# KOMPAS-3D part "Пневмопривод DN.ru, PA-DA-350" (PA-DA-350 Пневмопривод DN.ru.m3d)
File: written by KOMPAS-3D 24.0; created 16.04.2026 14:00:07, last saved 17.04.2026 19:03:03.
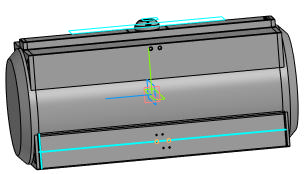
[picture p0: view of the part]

Document properties: Автор: DN.ru; Полное имя файла: C:\Работа\PA-DA-х Пневмопривод DN.ru\350\исходные материалы\PA-DA-350 Пневмопривод DN.ru.m3d

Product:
- Body: Тело 1  | qty 1
    Масса: 988.452769
- Body: Тело 2  | qty 1
    Масса: 988.452769
- Part/product: Пневмопривод DN.ru  | designation PA-DA-350
    Масса: 186
    Раздел спецификации: Прочие изделия
    Примечание: D290-00303

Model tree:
1. Эскиз:1
2. Элемент выдавливания:1
3. Эскиз:2  (with: Ребро.Элемент выдавливания:1)
4. Элемент выдавливания:2
5. Эскиз:3  (with: Ребро.Элемент выдавливания:2)
6. Элемент выдавливания:3  (with: Грань.Элемент выдавливания:2)
     Смещение 1 = -2; Расстояние 2 = 418; Смещение 2 = -2
7. Эскиз:4  (with: Грань.Элемент выдавливания:3)
8. Элемент выдавливания:4
9. Эскиз:6  (with: Ребро.Элемент выдавливания:2, Ребро.Элемент выдавливания:1)
10. Элемент выдавливания:6
11. Средняя плоскость:1  (with: Грань.Элемент выдавливания:6)
12. Отверстие:2  (with: Грань.Элемент выдавливания:6)
     Глубина выреза = 10; Диаметр отверстия = 6; Угол конуса дна = 120; Расстояние 2 = -22.5
13. Массив по сетке:2  (with: Отверстие:2)  (3 pattern instances)
     Шаг 1 = 20; Угол раствора = 90; Шаг 2 = 45
14. Массив по сетке:3  (with: Отверстие:2)  (2 pattern instances)
     Шаг 1 = 45; Угол раствора = 90; Шаг 2 = 20
15. Отверстие:3  (with: Грань.Элемент выдавливания:6)  (labels: W 1/2'')
     Глубина выреза = 10; Диаметр отверстия = 9.98886; Угол конуса дна = 120; Расстояние 1 = 20
16. W 1/2''  (with: Грань.Отверстие:3, Грань.Элемент выдавливания:6)  (labels: cil5_ex_DIN 477 BSW coarse)
     Длина резьбы = 8; Шаг резьбы = 2.117; Номинальный диаметр резьбы = 12.7
17. Массив по сетке:4  (with: Отверстие:3)  (labels: W 1/2'')  (2 pattern instances)
18. W 1/4''  (with: Грань.Отверстие:3, Грань.Элемент выдавливания:6)  (labels: cil5_ex_DIN 477 BSW coarse)
     Длина резьбы = 8; Шаг резьбы = 2.117; Номинальный диаметр резьбы = 12.7; Шаг 1 = 40; Угол раствора = 90; Шаг 2 = 10
19. Эскиз:7  (with: Грань.Элемент выдавливания:2)
20. Элемент выдавливания:7
21. Эскиз:8  (with: Грань.Элемент выдавливания:2, Ребро.Элемент выдавливания:2)
22. Элемент выдавливания:8  (with: Грань.Элемент выдавливания:6)
     Расстояние 2 = 4
23. Отверстие:4  (with: Грань.Элемент выдавливания:2)
     Глубина выреза = 7; Диаметр отверстия = 10; Угол конуса дна = 118; Расстояние 1 = 15; Расстояние 2 = 15; Диаметр зенковки = 13.2; Глубина зенковки = 1.6; Угол зенковки = 90
24. Массив по сетке:5  (with: Отверстие:4)  (2 pattern instances)
     Шаг 1 = 30; Угол раствора = 90
25. Отверстие:5  (with: Грань.Элемент выдавливания:3)
     Глубина выреза = 10; Диаметр отверстия = 5; Угол конуса дна = 120; Диаметр зенковки = 7; Глубина зенковки = 1; Угол зенковки = 90
26. Массив по сетке:6  (with: Отверстие:5)  (4 pattern instances)
     Угол раствора = 90
27. Фаска:1  (with: Ребро.Элемент выдавливания:4)
     Угол = 45; Длина 1 = 15; Длина 2 = 15
28. Скругление:2  (with: Ребро.Элемент выдавливания:3)
     Радиус = 2
29. Скругление:3  (with: Ребро.Элемент выдавливания:6)
     Радиус = 3
30. Скругление:4  (with: Ребро.Элемент выдавливания:8, Ребро.Элемент выдавливания:2)
     Радиус = 2
31. Скругление:5  (with: Ребро.Элемент выдавливания:6)
     Радиус = 3
32. Смещенная плоскость:1  (with: Грань.Элемент выдавливания:3)
33. Эскиз:9
34. Элемент выдавливания:9  (with: Грань.Фаска:1)
     Расстояние 1 = 43.4142; Смещение 1 = 1
35. Смещенная плоскость:2  (with: Грань.Элемент выдавливания:4)
     Расстояние = 0.5
36. Эскиз:10
37. Элемент выдавливания:10
     Расстояние 1 = 25.9142
38. Эскиз:11  (with: Грань.Элемент выдавливания:4)
39. Элемент выдавливания:11
     Расстояние 1 = 1
40. Эскиз:12  (with: Грань.Элемент выдавливания:11, Ребро.Элемент выдавливания:11)
41. Элемент выдавливания:12  (with: Грань.Элемент выдавливания:4)
     Расстояние 2 = 1
42. Эскиз:13  (with: Грань.Элемент выдавливания:11)
43. Элемент выдавливания:13  (with: Грань.Элемент выдавливания:4)
     Расстояние 2 = 1
44. Скругление:7  (with: Ребро.Элемент выдавливания:11)
     Радиус = 1
45. Скругление:8  (with: Ребро.Элемент выдавливания:8)
     Радиус = 2
46. Эскиз:14  (with: Грань.Элемент выдавливания:3)
47. Элемент выдавливания:14  (with: Грань.Фаска:1)
     Расстояние 1 = 54.1414; Смещение 1 = 0.1
48. Эскиз:15  (with: Грань.Элемент выдавливания:3, Ребро.Скругление:2)
49. Элемент выдавливания:15
     Расстояние 2 = 0.1
50. Отверстие:6  (with: Грань.Элемент выдавливания:2, Ребро.Элемент выдавливания:2)
     Глубина выреза = 10; Диаметр отверстия = 20; Угол конуса дна = 118; Расстояние 1 = 35; Расстояние 2 = 35; Диаметр цековки = 35; Глубина цековки = 5
51. Зеркальный массив:1
52. Экземпляр ( 1 )
53. Экземпляр ( 2 )  (with: Отверстие:6)
54. Зеркальный массив:2  (with: Экземпляр ( 1 ), Экземпляр ( 2 ), Отверстие:6)
55. Зеркальный массив:3  (with: Экземпляр ( 1 ), Экземпляр ( 2 ), Зеркальный массив:2, Отверстие:6)
56. Зеркальный массив:4  (with: Экземпляр ( 1 ), Экземпляр ( 2 ), Зеркальный массив:1, Отверстие:6, Зеркальный массив:3, Зеркальный массив:2)
57. Фаска:2  (with: Ребро.Элемент выдавливания:7)
     Угол = 45; Длина 1 = 2; Длина 2 = 2
58. Фаска:3  (with: Ребро.Элемент выдавливания:1)
     Угол = 45; Длина 1 = 30; Длина 2 = 30
59. Фаска:4  (with: Ребро.Элемент выдавливания:7)
     Угол = 45; Длина 1 = 2.5; Длина 2 = 2.5
60. Смещенная плоскость:3  (with: Грань.Элемент выдавливания:6)
     Расстояние = 5
61. Эскиз:16
62. Элемент выдавливания:16
     Расстояние 2 = 0.1
63. Зеркальный массив:5  (with: Экземпляр ( 1 ), Экземпляр ( 2 ), Элемент выдавливания:16)

Expressions: H/2; -G/2; v2053*2; (E-D-6)/2
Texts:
  PA-DA-350
  GOST 26.020 Pr3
